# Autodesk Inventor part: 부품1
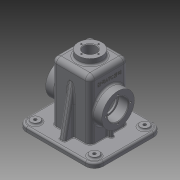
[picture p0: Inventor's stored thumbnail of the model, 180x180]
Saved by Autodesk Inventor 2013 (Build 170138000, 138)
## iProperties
Created: 2016-01
Part Number: 부품1
Material: 일반
Document SubType Name: Modeling
Designer: Administrator
Density: 1 g/cm^3
Author: Administrator
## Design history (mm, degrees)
sketch "스케치1"
  geometry: L1 (-65, 57.5)-(65, 57.5); L2 (65, 57.5)-(65, -57.5); L3 (65, -57.5)-(-65, -57.5); L4 (-65, -57.5)-(-65, 57.5); 3 further points
  constraints: 8 end point, 2 midpoint, 2 parallel, 1 horizontal, 1 horizontal alignment, 1 perpendicular, 1 vertical alignment
  dimensions: "d0" = 130 distance of L1.start L1.end; "d2" = 115 distance of L1.end L2.end
extrude "돌출1" new body sketch "스케치1" distance "d3" = 8; taper "d4" = 0 deg
sketch "스케치2"
  geometry: L1 (60, -52.5)-(-60, -52.5); L2 (-60, -52.5)-(-60, 52.5); L3 (-60, 52.5)-(60, 52.5); L4 (60, 52.5)-(60, -52.5); 3 further points
  constraints: 8 end point, 2 midpoint, 2 parallel, 1 horizontal, 1 horizontal alignment, 1 perpendicular, 1 vertical alignment
  dimensions: "d5" = 120 distance of L1.start L1.end; "d7" = 105 distance of L1.end L2.end
extrude "돌출2" join sketch "스케치2" distance "d8" = 2; taper "d9" = 0 deg
sketch "스케치3"
  geometry: L1 (-32.5, 32.5)-(32.5, 32.5); L2 (32.5, 32.5)-(32.5, -32.5); L3 (32.5, -32.5)-(-32.5, -32.5); L4 (-32.5, -32.5)-(-32.5, 32.5); 3 further points
  constraints: 8 end point, 2 midpoint, 2 parallel, 1 horizontal, 1 horizontal alignment, 1 perpendicular, 1 vertical alignment
  dimensions: "d10" = 65 distance of L1.start L1.end; "d12" = 65 distance of L1.end L2.end
extrude "돌출3" join sketch "스케치3" distance "d13" = 100; taper "d14" = 0 deg
fillet "모깎기1" dims "d15" = 15
sketch "스케치4"
  geometry: C1 r 7.5 at (-50, 42.5); C2 r 7.5 at (-50, -42.5); C3 r 7.5 at (50, -42.5); C4 r 7.5 at (50, 42.5); A1 r 15 centre (-50, 42.5) between (-50, 57.5) and (-65, 42.5) reference; A2 r 15 centre (-50, -42.5) between (-65, -42.5) and (-50, -57.5) reference; A3 r 15 centre (50, -42.5) between (50, -57.5) and (65, -42.5) reference; A4 r 15 centre (50, 42.5) between (65, 42.5) and (50, 57.5) reference; 1 further point
  constraints: 4 centre point, 4 coincident
  dimensions: "d16" = 15 diameter of C1; "d17" = 15 diameter of C2; "d18" = 15 diameter of C3; "d19" = 15 diameter of C4
extrude "돌출4" join sketch "스케치4" distance "d20" = 3; taper "d21" = 0 deg
hole "구멍1" diameter "d25" = 5; stored, may be unused: countersink angle "d29" = 90 deg, drill point angle "d31" = 0 deg; dims "d23" = 10, "d24" = 10, "d26" = 6, "d27" = 4, "d28" = 2, "d30" = 8
hole "구멍2" diameter "d34" = 5; stored, may be unused: countersink angle "d38" = 90 deg, drill point angle "d40" = 0 deg; dims "d32" = 10, "d33" = 10, "d35" = 6, "d36" = 4, "d37" = 2, "d39" = 8
hole "구멍3" diameter "d43" = 5; stored, may be unused: countersink angle "d47" = 90 deg, drill point angle "d49" = 0 deg; dims "d41" = 10, "d42" = 10, "d44" = 6, "d45" = 4, "d46" = 2, "d48" = 8
hole "구멍4" diameter "d52" = 5; stored, may be unused: countersink angle "d56" = 90 deg, drill point angle "d58" = 0 deg; dims "d50" = 10, "d51" = 10, "d53" = 6, "d54" = 4, "d55" = 2, "d57" = 8
sketch "스케치6"
  geometry: L1 (-27.5, -27.5)-(27.5, -27.5); L2 (27.5, -27.5)-(27.5, 27.5); L3 (27.5, 27.5)-(-27.5, 27.5); L4 (-27.5, 27.5)-(-27.5, -27.5); 3 further points
  constraints: 8 end point, 2 midpoint, 2 parallel, 1 horizontal, 1 horizontal alignment, 1 perpendicular, 1 vertical alignment
  dimensions: "d60" = 55 distance of L3.end L1.start; "d62" = 55 distance of L2.end L3.end
extrude "돌출5" cut sketch "스케치6" distance "d63" = 105; taper "d64" = 0 deg
sketch "스케치7"
  geometry: L1 (32.5, 108)-(32.5, 8) reference; L2 (32.5, 8)-(57.5, 8) reference; L3 (57.5, 8)-(57.5, 0) reference; L4 (57.5, 0)-(52.5, 0) reference; L5 (52.5, 0)-(52.5, -2) reference; L6 (52.5, -2)-(27.5, -2) reference; L7 (27.5, -2)-(27.5, 103) reference; L8 (27.5, 103)-(-27.5, 103) reference; L9 (-27.5, 103)-(-27.5, -2) reference; L10 (-27.5, -2)-(-52.5, -2) reference; L11 (-52.5, -2)-(-52.5, 0) reference; L12 (-52.5, 0)-(-57.5, 0) reference; L13 (-57.5, 0)-(-57.5, 8) reference; L14 (-57.5, 8)-(-32.5, 8) reference; L15 (-32.5, 8)-(-32.5, 108) reference; L16 (-32.5, 108)-(32.5, 108) reference; L17 (-57.5, 8)-(-42.5, 8) reference; L18 (-48.184, 8)-(-32.5, 87.642); L19 (-32.5, 8)-(-32.5, 108) reference; 1 further point
  constraints: 2 end point, 2 point on line
feature "리브1" sketch "스케치7" dims "d65" = 1, "d66" = 10, "d67" = 0, "d68" = 0, "d69" = 1, "d70" = 1
sketch "스케치8"
  geometry: L1 (8, 90)-(8, 85) reference; L2 (8, 85)-(10, 85) reference; L3 (10, 85)-(10, -20) reference; L4 (10, -20)-(8, -20) reference; L5 (8, -20)-(8, -25) reference; L6 (8, -25)-(0, -25) reference; L7 (0, -25)-(0, 0) reference; L8 (0, 0)-(0, 65) reference; L9 (0, 65)-(0, 90) reference; L10 (0, 90)-(8, 90) reference; L11 (0, 0)-(-100, 0) reference; L12 (-100, 0)-(-100, 65) reference; L13 (-100, 65)-(0, 65) reference; L14 (10, 85)-(10, -20) reference; L15 (10, 32.5)-(-45, 32.5); C1 r 27.5 at (-45, 32.5); 1 further point
  constraints: 2 end point, 1 centre point, 1 coincident, 1 horizontal, 1 midpoint
  dimensions: "d71" = 55 distance of L15.start L15.end; "d72" = 55 diameter of C1
extrude "돌출6" join sketch "스케치8" distance "d73" = 15; taper "d74" = 0 deg
sketch "스케치9"
  geometry: C1 r 27.5 at (0, 0) reference; 1 further point
hole "구멍5" sketch "스케치9" at (0, 0) diameter "d75" = 30; stored, may be unused: countersink angle "d79" = 82 deg, drill point angle "d81" = 0 deg; dims "d76" = 6, "d77" = 35, "d78" = 17, "d80" = 30
sketch "스케치11"
  geometry: L1 (0, 0)-(-21, 0); C1 r 27.5 at (0, 0) reference; 1 further point
  constraints: 2 end point, 1 horizontal
  dimensions: "d82" = 21 distance of L1.start L1.end
hole "구멍6" sketch "스케치11" at (-21, 0) diameter "d83" = 3.242; stored, may be unused: countersink angle "d87" = 82 deg, drill point angle "d89" = 118 deg; dims "d84" = 8, "d85" = 35, "d86" = 17, "d88" = 10
sketch "스케치13"
  geometry: L1 (27.5, 103)-(-27.5, 103) reference; L2 (-27.5, 103)-(-27.5, 68) reference; L3 (-27.5, 68)-(-30.5, 68) reference; L4 (-30.5, 68)-(-30.5, 70.5) reference; L5 (-30.5, 70.5)-(-47.5, 70.5) reference; L6 (-47.5, 70.5)-(-47.5, 72.379) reference; L7 (-47.5, 72.379)-(-37.5, 72.379) reference; L8 (-37.5, 72.379)-(-36.526, 74) reference; L9 (-36.526, 74)-(-37.5, 75.621) reference; L10 (-37.5, 75.621)-(-47.5, 75.621) reference; L11 (-47.5, 75.621)-(-47.5, 80.5) reference; L12 (-47.5, 80.5)-(-32.5, 80.5) reference; L13 (-32.5, 80.5)-(-32.5, 108) reference; L14 (-32.5, 108)-(32.5, 108) reference; L15 (32.5, 108)-(32.5, 80.5) reference; L16 (32.5, 80.5)-(47.5, 80.5) reference; L17 (47.5, 80.5)-(47.5, 75.621) reference; L18 (47.5, 75.621)-(37.5, 75.621) reference; L19 (37.5, 75.621)-(36.526, 74) reference; L20 (36.526, 74)-(37.5, 72.379) reference; L21 (37.5, 72.379)-(47.5, 72.379) reference; L22 (47.5, 72.379)-(47.5, 70.5) reference; L23 (47.5, 70.5)-(30.5, 70.5) reference; L24 (30.5, 70.5)-(30.5, 68) reference; L25 (30.5, 68)-(27.5, 68) reference; L26 (27.5, 68)-(27.5, 103) reference; L27 (65, 0)-(60, 0) reference; L28 (60, 0)-(60, -2) reference; L29 (60, -2)-(27.5, -2) reference; L30 (27.5, -2)-(27.5, 38) reference; L31 (27.5, 38)-(30.5, 38) reference; L32 (30.5, 38)-(30.5, 35.5) reference; L33 (30.5, 35.5)-(47.5, 35.5) reference; L34 (47.5, 35.5)-(47.5, 33.621) reference; L35 (47.5, 33.621)-(37.5, 33.621) reference; L36 (37.5, 33.621)-(36.526, 32) reference; L37 (36.526, 32)-(37.5, 30.379) reference; L38 (37.5, 30.379)-(47.5, 30.379) reference; L39 (47.5, 30.379)-(47.5, 25.5) reference; L40 (47.5, 25.5)-(32.5, 25.5) reference; L41 (32.5, 25.5)-(32.5, 8) reference; L42 (32.5, 8)-(65, 8) reference; L43 (65, 8)-(65, 0) reference; L44 (-60, 0)-(-65, 0) reference; L45 (-65, 0)-(-65, 8) reference; L46 (-65, 8)-(-32.5, 8) reference; L47 (-32.5, 8)-(-32.5, 25.5) reference; L48 (-32.5, 25.5)-(-47.5, 25.5) reference; L49 (-47.5, 25.5)-(-47.5, 30.379) reference; L50 (-47.5, 30.379)-(-37.5, 30.379) reference; L51 (-37.5, 30.379)-(-36.526, 32) reference; L52 (-36.526, 32)-(-37.5, 33.621) reference; L53 (-37.5, 33.621)-(-47.5, 33.621) reference; L54 (-47.5, 33.621)-(-47.5, 35.5) reference; L55 (-47.5, 35.5)-(-30.5, 35.5) reference; L56 (-30.5, 35.5)-(-30.5, 38) reference; L57 (-30.5, 38)-(-27.5, 38) reference; L58 (-27.5, 38)-(-27.5, -2) reference; L59 (-27.5, -2)-(-60, -2) reference; L60 (-60, -2)-(-60, 0) reference; L61 (-50, 8)-(50, 8) reference; L62 (39, 8)-(39, 25.5); 1 further point
  constraints: 2 end point, 2 point on line, 1 vertical
feature "리브2" sketch "스케치13" dims "d93" = 1, "d94" = 6, "d95" = 0, "d96" = 0, "d97" = 1, "d98" = 1
sketch "스케치14"
  geometry: C1 r 20 at (0, 0); 1 further point
  constraints: 1 centre point, 1 coincident
  dimensions: "d99" = 40 diameter of C1
extrude "돌출7" join sketch "스케치14" distance "d100" = 10; taper "d101" = 0 deg
hole "구멍7" diameter "d104" = 21; stored, may be unused: countersink angle "d108" = 82 deg, drill point angle "d110" = 0 deg; dims "d102" = 10, "d103" = 10, "d105" = 8, "d106" = 35, "d107" = 17, "d109" = 10
sketch "스케치16"
  geometry: L1 (0, 0)-(14.5, 0); C1 r 20 at (0, 0) reference
  constraints: 2 end point, 1 horizontal
  dimensions: "d111" = 14.5 distance of L1.start L1.end
hole "구멍8" sketch "스케치16" at (14.5, 0) diameter "d112" = 2.459; stored, may be unused: countersink angle "d116" = 82 deg, drill point angle "d118" = 0 deg; dims "d113" = 7, "d114" = 35, "d115" = 17, "d117" = 9
fillet "모깎기2" dims "d122" = 8
fillet "모깎기3" dims "d123" = 8
fillet "모깎기5" dims "d125" = 10
fillet "모깎기7" dims "d127" = 0.3
chamfer "모따기1" distance "d128" = 1; stored, may be unused: second distance "d129" = 2, angle "d130" = 45 deg
sketch "스케치17"
  geometry: L1 (53, -52.5)-(53, -57.5) reference; L2 (53, -57.5)-(45, -57.5) reference; L3 (45, -57.5)-(45, -24.5) reference; L4 (45, -24.5)-(45, -3) reference; L5 (45, -3)-(27.336, -3) reference; L6 (-12.49, -24.5)-(-47, -24.5) reference; L7 (-47, -24.5)-(-47, 24.5) reference; L8 (-12.49, 24.5)-(-47, 24.5) reference; L9 (45, 24.5)-(12.49, 24.5) reference; L10 (45, 3)-(45, 24.5) reference; L11 (27.336, 3)-(45, 3) reference; L12 (55, -52.5)-(53, -52.5) reference; L13 (55, 52.5)-(55, -52.5) reference; L14 (53, 52.5)-(55, 52.5) reference; L15 (53, 57.5)-(53, 52.5) reference; L16 (45, 57.5)-(53, 57.5) reference; L17 (45, 24.5)-(45, 57.5) reference; L18 (45, -24.5)-(12.49, -24.5) reference; L19 (-65, -1.229)-(-65, 1.23) reference; L20 (-65, 0)-(-38, 0); C1 r 17.5 at (0, 0) reference; A1 r 27.5 centre (0, 0) between (-12.49, 24.5) and (-12.49, -24.5) reference; A2 r 27.5 centre (0, 0) between (12.49, -24.5) and (27.336, -3) reference; A3 r 27.5 centre (0, 0) between (-12.49, -24.5) and (12.49, -24.5) reference; A4 r 27.5 centre (0, 0) between (12.49, 24.5) and (-12.49, 24.5) reference; A5 r 27.5 centre (0, 0) between (27.336, 3) and (12.49, 24.5) reference; A6 r 27.5 centre (0, 0) between (-12.49, 24.5) and (-12.49, -24.5) reference; 2 further points
  constraints: 2 end point, 1 coincident, 1 horizontal, 1 horizontal alignment, 1 midpoint, 1 other
  dimensions: "d131" = 27 distance of L20.start L20.end
feature "엠보싱1" sketch "스케치17" dims "d10" = 65, "d12" = 65, "d132" = 0.5, "d133" = 0
fillet "모깎기8" dims "d134" = 3
fillet "모깎기9" dims "d135" = 3
fillet "모깎기14" dims "d140" = 3
fillet "모깎기15" dims "d141" = 3
fillet "모깎기16" dims "d142" = 3
fillet "모깎기17" dims "d143" = 3
fillet "모깎기18" dims "d144" = 3
fillet "모깎기19" dims "d145" = 1
fillet "모깎기20" dims "d146" = 3
fillet "모깎기21" dims "d147" = 3
node "솔리드1"
mirror "대칭1"
pattern_circular "원형 패턴1" dims angle "d91" = 360 deg
mirror "대칭2"
mirror "대칭3"
pattern_circular "원형 패턴2" dims angle "d120" = 360 deg
node "절단 모서리 투영1"
node "절단 모서리 투영2"
node "절단 모서리 투영3"
node "절단 모서리 투영4"
